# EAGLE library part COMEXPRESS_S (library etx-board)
ETX Express COM Express Device generated with split-gate-in-device-to-single-gates.ulp from C-5353652-36-3.dev at 04.12.08 14:01:30 with EAGLE Version 5.3.5 Copyright (c) 1988-2008 CadSoft Source: http://catalog.tycoelectronics.com .. ENG_CS_889092_0.5mm_FH_Conn_0906.pdf http://nordic.kontron.com/searchresult/?searchterm=etxe_designguide_v1.4.pdf
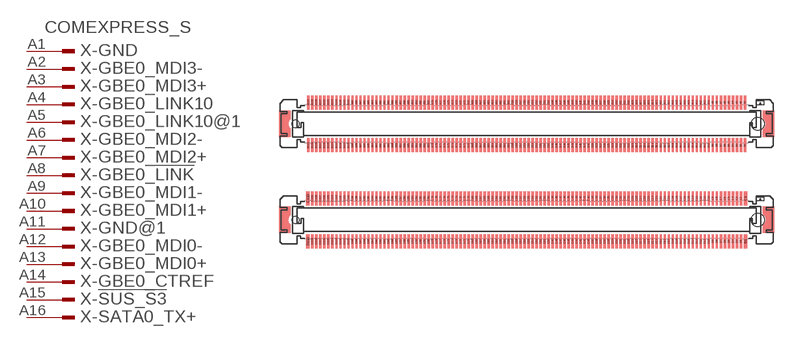
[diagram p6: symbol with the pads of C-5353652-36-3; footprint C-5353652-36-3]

Designator prefix X; gates -GND=1PIN_NAME_VALUE -GBE0_MDI3-=1PIN_NAME -GBE0_MDI3+=1PIN_NAME -GBE0_LINK10=1PIN_NAME -GBE0_LINK10@1=1PIN_NAME -GBE0_MDI2-=1PIN_NAME -GBE0_MDI2+=1PIN_NAME -GBE0_!LINK=1PIN_NAME -GBE0_MDI1-=1PIN_NAME -GBE0_MDI1+=1PIN_NAME -GND@1=1PIN_NAME -GBE0_MDI0-=1PIN_NAME -GBE0_MDI0+=1PIN_NAME -GBE0_CTREF=1PIN_NAME -!SUS_S3=1PIN_NAME -SATA0_TX+=1PIN_NAME -SATA0_TX-=1PIN_NAME -!SUS_S4=1PIN_NAME -SATA0_RX+=1PIN_NAME -SATA0_RX-=1PIN_NAME -GND@2=1PIN_NAME -SATA2_TX+=1PIN_NAME -SATA2_TX-=1PIN_NAME -!SUS_S5=1PIN_NAME -SATA2_RX+=1PIN_NAME -SATA2_RX-=1PIN_NAME -!BATLOW=1PIN_NAME -!ATA_ACT=1PIN_NAME -AC_SYNC=1PIN_NAME -!AC_RST=1PIN_NAME -GND@3=1PIN_NAME -AC_BITCLK=1PIN_NAME -AC_SDOUT=1PIN_NAME -BIOS_DISABLE=1PIN_NAME -!THRMTRIP=1PIN_NAME -USB6-=1PIN_NAME -USB6+=1PIN_NAME -!USB_6_7_OC=1PIN_NAME -USB4-=1PIN_NAME -USB4+=1PIN_NAME -GND@4=1PIN_NAME -USB2-=1PIN_NAME -USB2+=1PIN_NAME -!USB_2_3_OC=1PIN_NAME -USB0-=1PIN_NAME -USB0+=1PIN_NAME -VCC_RTC=1PIN_NAME -!EXCD0_PERST=1PIN_NAME -!EXCD0_CPPE=1PIN_NAME -LPC_SERIRQ=1PIN_NAME -GND@5=1PIN_NAME -PCIE_TX5+=1PIN_NAME -PCIE_TX5-=1PIN_NAME -GPI0=1PIN_NAME -PCIE_TX4+=1PIN_NAME -PCIE_TX4-=1PIN_NAME -GND@6=1PIN_NAME -PCIE_TX3+=1PIN_NAME -PCIE_TX3-=1PIN_NAME -GND@7=1PIN_NAME -PCIE_TX2+=1PIN_NAME -PCIE_TX2-=1PIN_NAME -GPI1=1PIN_NAME -PCIE_TX1+=1PIN_NAME -PCIE_TX1-=1PIN_NAME -GND@8=1PIN_NAME -GPI2=1PIN_NAME -PCIE_TX0+=1PIN_NAME -PCIE_TX0-=1PIN_NAME -GND@9=1PIN_NAME -LVDS_A0+=1PIN_NAME -LVDS_A0-=1PIN_NAME -LVDS_A1+=1PIN_NAME -LVDS_A1-=1PIN_NAME -LVDS_A2+=1PIN_NAME -LVDS_A2-=1PIN_NAME -LVDS_VDD_EN=1PIN_NAME -LVDS_A3+=1PIN_NAME -LVDS_A3-=1PIN_NAME -GND@10=1PIN_NAME -LVDS_A_CK+=1PIN_NAME -LVDS_A_CK-=1PIN_NAME -LVDS_I2C_CK=1PIN_NAME -LVDS_I2C_DAT=1PIN_NAME -GPI3=1PIN_NAME -!KBD_RST=1PIN_NAME -KBD_A20GATE=1PIN_NAME -PCIE0_CK_REF+=1PIN_NAME -PCIE0_CK_REF-=1PIN_NAME -GND@11=1PIN_NAME -RSVD=1PIN_NAME -RSVD@1=1PIN_NAME -GPO0=1PIN_NAME -RSVD@2=1PIN_NAME -RSVD@3=1PIN_NAME -GND@12=1PIN_NAME -VCC_12V=1PIN_NAME -VCC_12V@1=1PIN_NAME -VCC_12V@2=1PIN_NAME -GND@13=1PIN_NAME -VCC_12V@3=1PIN_NAME -VCC_12V@4=1PIN_NAME -VCC_12V@5=1PIN_NAME -VCC_12V@6=1PIN_NAME -VCC_12V@7=1PIN_NAME -VCC_12V@8=1PIN_NAME -VCC_12V@9=1PIN_NAME -VCC_12V@10=1PIN_NAME -VCC_12V@11=1PIN_NAME -GND@14=1PIN_NAME -GND@15=1PIN_NAME -GBE0_ACT=1PIN_NAME -LPC_FRAME!=1PIN_NAME -LPC_AD0=1PIN_NAME -LPC_AD1=1PIN_NAME -LPC_AD2=1PIN_NAME -LPC_AD3=1PIN_NAME -!LPC_DRQ0=1PIN_NAME -LPC_DRQ1!=1PIN_NAME -LPC_CLK=1PIN_NAME -GND@16=1PIN_NAME -!PWRBTN=1PIN_NAME -SMB_CK=1PIN_NAME -SMB_DAT=1PIN_NAME -SMB_ALERT!=1PIN_NAME -SATA1_TX+=1PIN_NAME -SATA1_TX-=1PIN_NAME -SUS_STAT!=1PIN_NAME -SATA1_RX+=1PIN_NAME -SATA1_RX-=1PIN_NAME -GND@17=1PIN_NAME -SATA3_TX+=1PIN_NAME -SATA3_TX-=1PIN_NAME -PWR_OK=1PIN_NAME -SATA3_RX+=1PIN_NAME -SATA3_RX-=1PIN_NAME -WDT=1PIN_NAME -AC_SDIN2=1PIN_NAME -AC_SDIN1=1PIN_NAME -AC_SDIN0=1PIN_NAME -GND@18=1PIN_NAME -SPKR=1PIN_NAME -I2C_CK=1PIN_NAME -I2C_DAT=1PIN_NAME -THRM!=1PIN_NAME -USB7-=1PIN_NAME -USB7+=1PIN_NAME -!USB_4_5_OC=1PIN_NAME -USB5-=1PIN_NAME -USB5+=1PIN_NAME -GND@19=1PIN_NAME -USB3-=1PIN_NAME -USB3+=1PIN_NAME -!USB_0_1_OC=1PIN_NAME -USB1-=1PIN_NAME -USB1+=1PIN_NAME -!EXCD1_PERST=1PIN_NAME -!EXCD1_CPPE=1PIN_NAME -!SYS_RESET=1PIN_NAME -!CB_RESET=1PIN_NAME -GND@20=1PIN_NAME -PCIE_RX5+=1PIN_NAME -PCIE_RX5-=1PIN_NAME -GPO1=1PIN_NAME -PCIE_RX4+=1PIN_NAME -PCIE_RX4-=1PIN_NAME -GPO2=1PIN_NAME -PCIE_RX3+=1PIN_NAME -PCIE_RX3-=1PIN_NAME -GND@21=1PIN_NAME -PCIE_RX2+=1PIN_NAME -PCIE_RX2-=1PIN_NAME -GPO3=1PIN_NAME -PCIE_RX1+=1PIN_NAME -PCIE_RX1-=1PIN_NAME -!WAKE0=1PIN_NAME -!WAKE1=1PIN_NAME -PCIE_RX0+=1PIN_NAME -PCIE_RX0-=1PIN_NAME -GND@22=1PIN_NAME -LVDS_B0+=1PIN_NAME -LVDS_B0-=1PIN_NAME -LVDS_B1+=1PIN_NAME -LVDS_B1-=1PIN_NAME -LVDS_B2+=1PIN_NAME -LVDS_B2-=1PIN_NAME -LVDS_B3+=1PIN_NAME -LVDS_B3-=1PIN_NAME -LVDS_BKLT_EN=1PIN_NAME -GND@23=1PIN_NAME -LVDS_B_CK+=1PIN_NAME -LVDS_B_CK-=1PIN_NAME -LVDS_BKLT_CTRL=1PIN_NAME -VCC_5V_SBY=1PIN_NAME -VCC_5V_SBY@1=1PIN_NAME -VCC_5V_SBY@2=1PIN_NAME -VCC_5V_SBY@3=1PIN_NAME -RSVD@4=1PIN_NAME -VGA_RED=1PIN_NAME -GND@24=1PIN_NAME -VGA_GRN=1PIN_NAME -VGA_BLU=1PIN_NAME -VGA_HSYNC=1PIN_NAME -VGA_VSYNC=1PIN_NAME -VGA_I2C_CK=1PIN_NAME -VGA_I2C_DAT=1PIN_NAME -TV_DAC_A=1PIN_NAME -TV_DAC_B=1PIN_NAME -TV_DAC_C=1PIN_NAME -GND@25=1PIN_NAME -VCC_12V@12=1PIN_NAME -VCC_12V@13=1PIN_NAME -VCC_12V@14=1PIN_NAME -VCC_12V@15=1PIN_NAME -VCC_12V@16=1PIN_NAME -VCC_12V@17=1PIN_NAME -VCC_12V@18=1PIN_NAME -VCC_12V@19=1PIN_NAME -VCC_12V@20=1PIN_NAME -GND@26=1PIN_NAME -GND@27=1PIN_NAME -IDE_D7=1PIN_NAME -IDE_D6=1PIN_NAME -IDE_D3=1PIN_NAME -IDE_D15=1PIN_NAME -IDE_D8=1PIN_NAME -IDE_D9=1PIN_NAME -IDE_D2=1PIN_NAME -IDE_D13=1PIN_NAME -IDE_D1=1PIN_NAME -GND@28=1PIN_NAME -IDE_D14=1PIN_NAME -IDE_IORDY=1PIN_NAME -!IDE_IOR=1PIN_NAME -!PCI_PME=1PIN_NAME -!PCI_GNT2=1PIN_NAME -!PCI_REQ2=1PIN_NAME -!PCI_GNT1=1PIN_NAME -!PCI_REQ1=1PIN_NAME -!PCI_GNT0=1PIN_NAME -GND@29=1PIN_NAME -!PCI_REQ0=1PIN_NAME -!PCI_RST=1PIN_NAME -PCI_AD0=1PIN_NAME -PCI_AD2=1PIN_NAME -PCI_AD4=1PIN_NAME -PCI_AD6=1PIN_NAME -PCI_AD8=1PIN_NAME -PCI_AD10=1PIN_NAME -PCI_AD12=1PIN_NAME -GND@30=1PIN_NAME -PCI_AD14=1PIN_NAME -PCI_C/!BE1=1PIN_NAME -!PCI_PERR=1PIN_NAME -!PCI_LOCK=1PIN_NAME -!PCI_DEVSEL=1PIN_NAME -!PCI_IRDY=1PIN_NAME -PCI_C/!BE2=1PIN_NAME -PCI_AD17=1PIN_NAME -PCI_AD19=1PIN_NAME -GND@31=1PIN_NAME -PCI_AD21=1PIN_NAME -PCI_AD23=1PIN_NAME -PCI_C/!BE3=1PIN_NAME -PCI_AD25=1PIN_NAME -PCI_AD27=1PIN_NAME -PCI_AD29=1PIN_NAME -PCI_AD31=1PIN_NAME -!PCI_IRQA=1PIN_NAME -!PCI_IRQB=1PIN_NAME -GND@32=1PIN_NAME -PEG_RX0+=1PIN_NAME -PEG_RX0-=1PIN_NAME -!TYPE0=1PIN_NAME -PEG_RX1+=1PIN_NAME -PEG_RX1-=1PIN_NAME -!TYPE1=1PIN_NAME -PEG_RX2+=1PIN_NAME -PEG_RX2-=1PIN_NAME -GND@33=1PIN_NAME -PEG_RX3+=1PIN_NAME -PEG_RX3-=1PIN_NAME -RSVD@5=1PIN_NAME -RSVD@6=1PIN_NAME -PEG_RX4+=1PIN_NAME -PEG_RX4-=1PIN_NAME -RSVD@7=1PIN_NAME -PEG_RX5+=1PIN_NAME -PEG_RX5-=1PIN_NAME -GND@34=1PIN_NAME -PEG_RX6+=1PIN_NAME -PEG_RX6-=1PIN_NAME -SDVO_DATA=1PIN_NAME -PEG_RX7+=1PIN_NAME -PEG_RX7-=1PIN_NAME -GND@35=1PIN_NAME -RSVD@8=1PIN_NAME -PEG_RX8+=1PIN_NAME -PEG_RX8-=1PIN_NAME -GND@36=1PIN_NAME -PEG_RX9+=1PIN_NAME -PEG_RX9-=1PIN_NAME -RSVD@9=1PIN_NAME -GND@37=1PIN_NAME -PEG_RX10+=1PIN_NAME -PEG_RX10-=1PIN_NAME -GND@38=1PIN_NAME -PEG_RX11+=1PIN_NAME -PEG_RX11-=1PIN_NAME -GND@39=1PIN_NAME -PEG_RX12+=1PIN_NAME -PEG_RX12-=1PIN_NAME -GND@40=1PIN_NAME -PEG_RX13+=1PIN_NAME -PEG_RX13-=1PIN_NAME -GND@41=1PIN_NAME -RSVD@10=1PIN_NAME -PEG_RX14+=1PIN_NAME -PEG_RX14-=1PIN_NAME -GND@42=1PIN_NAME -PEG_RX15+=1PIN_NAME -PEG_RX15-=1PIN_NAME -GND@43=1PIN_NAME -VCC_12V@21=1PIN_NAME -VCC_12V@22=1PIN_NAME -VCC_12V@23=1PIN_NAME -VCC_12V@24=1PIN_NAME -VCC_12V@25=1PIN_NAME -VCC_12V@26=1PIN_NAME -GND@44=1PIN_NAME -GND@45=1PIN_NAME -IDE_D5=1PIN_NAME -IDE_D10=1PIN_NAME -IDE_D11=1PIN_NAME -IDE_D12=1PIN_NAME -IDE_D4=1PIN_NAME -IDE_D0=1PIN_NAME -IDE_REQ=1PIN_NAME -!IDE_IOW=1PIN_NAME -!IDE_ACK=1PIN_NAME -GND@46=1PIN_NAME -IDE_IRQ=1PIN_NAME -IDE_A0=1PIN_NAME -IDE_A1=1PIN_NAME -IDE_A2=1PIN_NAME -!IDE_CS1=1PIN_NAME -!IDE_CS3=1PIN_NAME -!IDE_RESET=1PIN_NAME -!PCI_GNT3=1PIN_NAME -!PCI_REQ3=1PIN_NAME -GND@47=1PIN_NAME -PCI_AD1=1PIN_NAME -PCI_AD3=1PIN_NAME -PCI_AD5=1PIN_NAME -PCI_AD7=1PIN_NAME -PCI_C/!BE0=1PIN_NAME -PCI_AD9=1PIN_NAME -PCI_AD11=1PIN_NAME -PCI_AD13=1PIN_NAME -PCI_AD15=1PIN_NAME -GND@48=1PIN_NAME -PCI_PAR=1PIN_NAME -!PCI_SERR=1PIN_NAME -!PCI_STOP=1PIN_NAME -!PCI_TRDY=1PIN_NAME -!PCI_FRAME=1PIN_NAME -PCI_AD16=1PIN_NAME -PCI_AD18=1PIN_NAME -PCI_AD20=1PIN_NAME -PCI_AD22=1PIN_NAME -GND@49=1PIN_NAME -PCI_AD24=1PIN_NAME -PCI_AD26=1PIN_NAME -PCI_AD28=1PIN_NAME -PCI_AD30=1PIN_NAME -!PCI_IRQC=1PIN_NAME -!PCI_IRQD=1PIN_NAME -!PCI_CLKRUN=1PIN_NAME -PCI_M66EN=1PIN_NAME -PCI_CLK=1PIN_NAME -GND@50=1PIN_NAME -PEG_TX0+=1PIN_NAME -PEG_TX0-=1PIN_NAME -!PEG_LANE_RV=1PIN_NAME -PEG_TX1+=1PIN_NAME -PEG_TX1-=1PIN_NAME -!TYPE2=1PIN_NAME -PEG_TX2+=1PIN_NAME -PEG_TX2-=1PIN_NAME -GND@51=1PIN_NAME -PEG_TX3+=1PIN_NAME -PEG_TX3-=1PIN_NAME -RSVD@11=1PIN_NAME -RSVD@12=1PIN_NAME -PEG_TX4+=1PIN_NAME -PEG_TX4-=1PIN_NAME -GND@52=1PIN_NAME -PEG_TX5+=1PIN_NAME -PEG_TX5-=1PIN_NAME -GND@53=1PIN_NAME -PEG_TX6+=1PIN_NAME -PEG_TX6-=1PIN_NAME -SDVO_CLK=1PIN_NAME -PEG_TX7+=1PIN_NAME -PEG_TX7-=1PIN_NAME -GND@54=1PIN_NAME -IDE_CBLID=1PIN_NAME -PEG_TX8+=1PIN_NAME -PEG_TX8-=1PIN_NAME -GND@55=1PIN_NAME -PEG_TX9+=1PIN_NAME -PEG_TX9-=1PIN_NAME -RSVD@13=1PIN_NAME -GND@56=1PIN_NAME -PEG_TX10+=1PIN_NAME -PEG_TX10-=1PIN_NAME -GND@57=1PIN_NAME -PEG_TX11+=1PIN_NAME -PEG_TX11-=1PIN_NAME -GND@58=1PIN_NAME -PEG_TX12+=1PIN_NAME -PEG_TX12-=1PIN_NAME -GND@59=1PIN_NAME -PEG_TX13+=1PIN_NAME -PEG_TX13-=1PIN_NAME -GND@60=1PIN_NAME -!PEG_ENABLE=1PIN_NAME -PEG_TX14+=1PIN_NAME -PEG_TX14-=1PIN_NAME -GND@61=1PIN_NAME -PEG_TX15+=1PIN_NAME -PEG_TX15-=1PIN_NAME -GND@62=1PIN_NAME -VCC_12V@27=1PIN_NAME -VCC_12V@28=1PIN_NAME -VCC_12V@29=1PIN_NAME -VCC_12V@30=1PIN_NAME -VCC_12V@31=1PIN_NAME -VCC_12V@32=1PIN_NAME -GND@63=1PIN_NAME

## COMEXPRESS_S  [C-5353652-36-3]
A1  -GND:1  pas
A2  -GBE0_MDI3-:1  pas
A3  -GBE0_MDI3+:1  pas
A4  -GBE0_LINK10:1  pas
A5  -GBE0_LINK10@1:1  pas
A6  -GBE0_MDI2-:1  pas
A7  -GBE0_MDI2+:1  pas
A8  -GBE0_!LINK:1  pas
A9  -GBE0_MDI1-:1  pas
A10  -GBE0_MDI1+:1  pas
A11  -GND@1:1  pas
A12  -GBE0_MDI0-:1  pas
A13  -GBE0_MDI0+:1  pas
A14  -GBE0_CTREF:1  pas
A15  -!SUS_S3:1  pas
A16  -SATA0_TX+:1  pas
A17  -SATA0_TX-:1  pas
A18  -!SUS_S4:1  pas
A19  -SATA0_RX+:1  pas
A20  -SATA0_RX-:1  pas
A21  -GND@2:1  pas
A22  -SATA2_TX+:1  pas
A23  -SATA2_TX-:1  pas
A24  -!SUS_S5:1  pas
A25  -SATA2_RX+:1  pas
A26  -SATA2_RX-:1  pas
A27  -!BATLOW:1  pas
A28  -!ATA_ACT:1  pas
A29  -AC_SYNC:1  pas
A30  -!AC_RST:1  pas
A31  -GND@3:1  pas
A32  -AC_BITCLK:1  pas
A33  -AC_SDOUT:1  pas
A34  -BIOS_DISABLE:1  pas
A35  -!THRMTRIP:1  pas
A36  -USB6-:1  pas
A37  -USB6+:1  pas
A38  -!USB_6_7_OC:1  pas
A39  -USB4-:1  pas
A40  -USB4+:1  pas
A41  -GND@4:1  pas
A42  -USB2-:1  pas
A43  -USB2+:1  pas
A44  -!USB_2_3_OC:1  pas
A45  -USB0-:1  pas
A46  -USB0+:1  pas
A47  -VCC_RTC:1  pas
A48  -!EXCD0_PERST:1  pas
A49  -!EXCD0_CPPE:1  pas
A50  -LPC_SERIRQ:1  pas
A51  -GND@5:1  pas
A52  -PCIE_TX5+:1  pas
A53  -PCIE_TX5-:1  pas
A54  -GPI0:1  pas
A55  -PCIE_TX4+:1  pas
A56  -PCIE_TX4-:1  pas
A57  -GND@6:1  pas
A58  -PCIE_TX3+:1  pas
A59  -PCIE_TX3-:1  pas
A60  -GND@7:1  pas
A61  -PCIE_TX2+:1  pas
A62  -PCIE_TX2-:1  pas
A63  -GPI1:1  pas
A64  -PCIE_TX1+:1  pas
A65  -PCIE_TX1-:1  pas
A66  -GND@8:1  pas
A67  -GPI2:1  pas
A68  -PCIE_TX0+:1  pas
A69  -PCIE_TX0-:1  pas
A70  -GND@9:1  pas
A71  -LVDS_A0+:1  pas
A72  -LVDS_A0-:1  pas
A73  -LVDS_A1+:1  pas
A74  -LVDS_A1-:1  pas
A75  -LVDS_A2+:1  pas
A76  -LVDS_A2-:1  pas
A77  -LVDS_VDD_EN:1  pas
A78  -LVDS_A3+:1  pas
A79  -LVDS_A3-:1  pas
A80  -GND@10:1  pas
A81  -LVDS_A_CK+:1  pas
A82  -LVDS_A_CK-:1  pas
A83  -LVDS_I2C_CK:1  pas
A84  -LVDS_I2C_DAT:1  pas
A85  -GPI3:1  pas
A86  -!KBD_RST:1  pas
A87  -KBD_A20GATE:1  pas
A88  -PCIE0_CK_REF+:1  pas
A89  -PCIE0_CK_REF-:1  pas
A90  -GND@11:1  pas
A91  -RSVD:1  pas
A92  -RSVD@1:1  pas
A93  -GPO0:1  pas
A94  -RSVD@2:1  pas
A95  -RSVD@3:1  pas
A96  -GND@12:1  pas
A97  -VCC_12V:1  pas
A98  -VCC_12V@1:1  pas
A99  -VCC_12V@2:1  pas
A100  -GND@13:1  pas
A101  -VCC_12V@3:1  pas
A102  -VCC_12V@4:1  pas
A103  -VCC_12V@5:1  pas
A104  -VCC_12V@6:1  pas
A105  -VCC_12V@7:1  pas
A106  -VCC_12V@8:1  pas
A107  -VCC_12V@9:1  pas
A108  -VCC_12V@10:1  pas
A109  -VCC_12V@11:1  pas
A110  -GND@14:1  pas
B1  -GND@15:1  pas
B2  -GBE0_ACT:1  pas
B3  -LPC_FRAME!:1  pas
B4  -LPC_AD0:1  pas
B5  -LPC_AD1:1  pas
B6  -LPC_AD2:1  pas
B7  -LPC_AD3:1  pas
B8  -!LPC_DRQ0:1  pas
B9  -LPC_DRQ1!:1  pas
B10  -LPC_CLK:1  pas
B11  -GND@16:1  pas
B12  -!PWRBTN:1  pas
B13  -SMB_CK:1  pas
B14  -SMB_DAT:1  pas
B15  -SMB_ALERT!:1  pas
B16  -SATA1_TX+:1  pas
B17  -SATA1_TX-:1  pas
B18  -SUS_STAT!:1  pas
B19  -SATA1_RX+:1  pas
B20  -SATA1_RX-:1  pas
B21  -GND@17:1  pas
B22  -SATA3_TX+:1  pas
B23  -SATA3_TX-:1  pas
B24  -PWR_OK:1  pas
B25  -SATA3_RX+:1  pas
B26  -SATA3_RX-:1  pas
B27  -WDT:1  pas
B28  -AC_SDIN2:1  pas
B29  -AC_SDIN1:1  pas
B30  -AC_SDIN0:1  pas
B31  -GND@18:1  pas
B32  -SPKR:1  pas
B33  -I2C_CK:1  pas
B34  -I2C_DAT:1  pas
B35  -THRM!:1  pas
B36  -USB7-:1  pas
B37  -USB7+:1  pas
B38  -!USB_4_5_OC:1  pas
B39  -USB5-:1  pas
B40  -USB5+:1  pas
B41  -GND@19:1  pas
B42  -USB3-:1  pas
B43  -USB3+:1  pas
B44  -!USB_0_1_OC:1  pas
B45  -USB1-:1  pas
B46  -USB1+:1  pas
B47  -!EXCD1_PERST:1  pas
B48  -!EXCD1_CPPE:1  pas
B49  -!SYS_RESET:1  pas
B50  -!CB_RESET:1  pas
B51  -GND@20:1  pas
B52  -PCIE_RX5+:1  pas
B53  -PCIE_RX5-:1  pas
B54  -GPO1:1  pas
B55  -PCIE_RX4+:1  pas
B56  -PCIE_RX4-:1  pas
B57  -GPO2:1  pas
B58  -PCIE_RX3+:1  pas
B59  -PCIE_RX3-:1  pas
B60  -GND@21:1  pas
B61  -PCIE_RX2+:1  pas
B62  -PCIE_RX2-:1  pas
B63  -GPO3:1  pas
B64  -PCIE_RX1+:1  pas
B65  -PCIE_RX1-:1  pas
B66  -!WAKE0:1  pas
B67  -!WAKE1:1  pas
B68  -PCIE_RX0+:1  pas
B69  -PCIE_RX0-:1  pas
B70  -GND@22:1  pas
B71  -LVDS_B0+:1  pas
B72  -LVDS_B0-:1  pas
B73  -LVDS_B1+:1  pas
B74  -LVDS_B1-:1  pas
B75  -LVDS_B2+:1  pas
B76  -LVDS_B2-:1  pas
B77  -LVDS_B3+:1  pas
B78  -LVDS_B3-:1  pas
B79  -LVDS_BKLT_EN:1  pas
B80  -GND@23:1  pas
B81  -LVDS_B_CK+:1  pas
B82  -LVDS_B_CK-:1  pas
B83  -LVDS_BKLT_CTRL:1  pas
B84  -VCC_5V_SBY:1  pas
B85  -VCC_5V_SBY@1:1  pas
B86  -VCC_5V_SBY@2:1  pas
B87  -VCC_5V_SBY@3:1  pas
B88  -RSVD@4:1  pas
B89  -VGA_RED:1  pas
B90  -GND@24:1  pas
B91  -VGA_GRN:1  pas
B92  -VGA_BLU:1  pas
B93  -VGA_HSYNC:1  pas
B94  -VGA_VSYNC:1  pas
B95  -VGA_I2C_CK:1  pas
B96  -VGA_I2C_DAT:1  pas
B97  -TV_DAC_A:1  pas
B98  -TV_DAC_B:1  pas
B99  -TV_DAC_C:1  pas
B100  -GND@25:1  pas
B101  -VCC_12V@12:1  pas
B102  -VCC_12V@13:1  pas
B103  -VCC_12V@14:1  pas
B104  -VCC_12V@15:1  pas
B105  -VCC_12V@16:1  pas
B106  -VCC_12V@17:1  pas
B107  -VCC_12V@18:1  pas
B108  -VCC_12V@19:1  pas
B109  -VCC_12V@20:1  pas
B110  -GND@26:1  pas
C1  -GND@27:1  pas
C2  -IDE_D7:1  pas
C3  -IDE_D6:1  pas
C4  -IDE_D3:1  pas
C5  -IDE_D15:1  pas
C6  -IDE_D8:1  pas
C7  -IDE_D9:1  pas
C8  -IDE_D2:1  pas
C9  -IDE_D13:1  pas
C10  -IDE_D1:1  pas
C11  -GND@28:1  pas
C12  -IDE_D14:1  pas
C13  -IDE_IORDY:1  pas
C14  -!IDE_IOR:1  pas
C15  -!PCI_PME:1  pas
C16  -!PCI_GNT2:1  pas
C17  -!PCI_REQ2:1  pas
C18  -!PCI_GNT1:1  pas
C19  -!PCI_REQ1:1  pas
C20  -!PCI_GNT0:1  pas
C21  -GND@29:1  pas
C22  -!PCI_REQ0:1  pas
C23  -!PCI_RST:1  pas
C24  -PCI_AD0:1  pas
C25  -PCI_AD2:1  pas
C26  -PCI_AD4:1  pas
C27  -PCI_AD6:1  pas
C28  -PCI_AD8:1  pas
C29  -PCI_AD10:1  pas
C30  -PCI_AD12:1  pas
C31  -GND@30:1  pas
C32  -PCI_AD14:1  pas
C33  -PCI_C/!BE1:1  pas
C34  -!PCI_PERR:1  pas
C35  -!PCI_LOCK:1  pas
C36  -!PCI_DEVSEL:1  pas
C37  -!PCI_IRDY:1  pas
C38  -PCI_C/!BE2:1  pas
C39  -PCI_AD17:1  pas
C40  -PCI_AD19:1  pas
C41  -GND@31:1  pas
C42  -PCI_AD21:1  pas
C43  -PCI_AD23:1  pas
C44  -PCI_C/!BE3:1  pas
C45  -PCI_AD25:1  pas
C46  -PCI_AD27:1  pas
C47  -PCI_AD29:1  pas
C48  -PCI_AD31:1  pas
C49  -!PCI_IRQA:1  pas
C50  -!PCI_IRQB:1  pas
C51  -GND@32:1  pas
C52  -PEG_RX0+:1  pas
C53  -PEG_RX0-:1  pas
C54  -!TYPE0:1  pas
C55  -PEG_RX1+:1  pas
C56  -PEG_RX1-:1  pas
C57  -!TYPE1:1  pas
C58  -PEG_RX2+:1  pas
C59  -PEG_RX2-:1  pas
C60  -GND@33:1  pas
C61  -PEG_RX3+:1  pas
C62  -PEG_RX3-:1  pas
C63  -RSVD@5:1  pas
C64  -RSVD@6:1  pas
C65  -PEG_RX4+:1  pas
C66  -PEG_RX4-:1  pas
C67  -RSVD@7:1  pas
C68  -PEG_RX5+:1  pas
C69  -PEG_RX5-:1  pas
C70  -GND@34:1  pas
C71  -PEG_RX6+:1  pas
C72  -PEG_RX6-:1  pas
C73  -SDVO_DATA:1  pas
C74  -PEG_RX7+:1  pas
C75  -PEG_RX7-:1  pas
C76  -GND@35:1  pas
C77  -RSVD@8:1  pas
C78  -PEG_RX8+:1  pas
C79  -PEG_RX8-:1  pas
C80  -GND@36:1  pas
C81  -PEG_RX9+:1  pas
C82  -PEG_RX9-:1  pas
C83  -RSVD@9:1  pas
C84  -GND@37:1  pas
C85  -PEG_RX10+:1  pas
C86  -PEG_RX10-:1  pas
C87  -GND@38:1  pas
C88  -PEG_RX11+:1  pas
C89  -PEG_RX11-:1  pas
C90  -GND@39:1  pas
C91  -PEG_RX12+:1  pas
C92  -PEG_RX12-:1  pas
C93  -GND@40:1  pas
C94  -PEG_RX13+:1  pas
C95  -PEG_RX13-:1  pas
C96  -GND@41:1  pas
C97  -RSVD@10:1  pas
C98  -PEG_RX14+:1  pas
C99  -PEG_RX14-:1  pas
C100  -GND@42:1  pas
C101  -PEG_RX15+:1  pas
C102  -PEG_RX15-:1  pas
C103  -GND@43:1  pas
C104  -VCC_12V@21:1  pas
C105  -VCC_12V@22:1  pas
C106  -VCC_12V@23:1  pas
C107  -VCC_12V@24:1  pas
C108  -VCC_12V@25:1  pas
C109  -VCC_12V@26:1  pas
C110  -GND@44:1  pas
D1  -GND@45:1  pas
D2  -IDE_D5:1  pas
D3  -IDE_D10:1  pas
D4  -IDE_D11:1  pas
D5  -IDE_D12:1  pas
D6  -IDE_D4:1  pas
D7  -IDE_D0:1  pas
D8  -IDE_REQ:1  pas
D9  -!IDE_IOW:1  pas
D10  -!IDE_ACK:1  pas
D11  -GND@46:1  pas
D12  -IDE_IRQ:1  pas
D13  -IDE_A0:1  pas
D14  -IDE_A1:1  pas
D15  -IDE_A2:1  pas
D16  -!IDE_CS1:1  pas
D17  -!IDE_CS3:1  pas
D18  -!IDE_RESET:1  pas
D19  -!PCI_GNT3:1  pas
D20  -!PCI_REQ3:1  pas
D21  -GND@47:1  pas
D22  -PCI_AD1:1  pas
D23  -PCI_AD3:1  pas
D24  -PCI_AD5:1  pas
D25  -PCI_AD7:1  pas
D26  -PCI_C/!BE0:1  pas
D27  -PCI_AD9:1  pas
D28  -PCI_AD11:1  pas
D29  -PCI_AD13:1  pas
D30  -PCI_AD15:1  pas
D31  -GND@48:1  pas
D32  -PCI_PAR:1  pas
D33  -!PCI_SERR:1  pas
D34  -!PCI_STOP:1  pas
D35  -!PCI_TRDY:1  pas
D36  -!PCI_FRAME:1  pas
D37  -PCI_AD16:1  pas
D38  -PCI_AD18:1  pas
D39  -PCI_AD20:1  pas
D40  -PCI_AD22:1  pas
D41  -GND@49:1  pas
D42  -PCI_AD24:1  pas
D43  -PCI_AD26:1  pas
D44  -PCI_AD28:1  pas
D45  -PCI_AD30:1  pas
D46  -!PCI_IRQC:1  pas
D47  -!PCI_IRQD:1  pas
D48  -!PCI_CLKRUN:1  pas
D49  -PCI_M66EN:1  pas
D50  -PCI_CLK:1  pas
D51  -GND@50:1  pas
D52  -PEG_TX0+:1  pas
D53  -PEG_TX0-:1  pas
D54  -!PEG_LANE_RV:1  pas
D55  -PEG_TX1+:1  pas
D56  -PEG_TX1-:1  pas
D57  -!TYPE2:1  pas
D58  -PEG_TX2+:1  pas
D59  -PEG_TX2-:1  pas
D60  -GND@51:1  pas
D61  -PEG_TX3+:1  pas
D62  -PEG_TX3-:1  pas
D63  -RSVD@11:1  pas
D64  -RSVD@12:1  pas
D65  -PEG_TX4+:1  pas
D66  -PEG_TX4-:1  pas
D67  -GND@52:1  pas
D68  -PEG_TX5+:1  pas
D69  -PEG_TX5-:1  pas
D70  -GND@53:1  pas
D71  -PEG_TX6+:1  pas
D72  -PEG_TX6-:1  pas
D73  -SDVO_CLK:1  pas
D74  -PEG_TX7+:1  pas
D75  -PEG_TX7-:1  pas
D76  -GND@54:1  pas
D77  -IDE_CBLID:1  pas
D78  -PEG_TX8+:1  pas
D79  -PEG_TX8-:1  pas
D80  -GND@55:1  pas
D81  -PEG_TX9+:1  pas
D82  -PEG_TX9-:1  pas
D83  -RSVD@13:1  pas
D84  -GND@56:1  pas
D85  -PEG_TX10+:1  pas
D86  -PEG_TX10-:1  pas
D87  -GND@57:1  pas
D88  -PEG_TX11+:1  pas
D89  -PEG_TX11-:1  pas
D90  -GND@58:1  pas
D91  -PEG_TX12+:1  pas
D92  -PEG_TX12-:1  pas
D93  -GND@59:1  pas
D94  -PEG_TX13+:1  pas
D95  -PEG_TX13-:1  pas
D96  -GND@60:1  pas
D97  -!PEG_ENABLE:1  pas
D98  -PEG_TX14+:1  pas
D99  -PEG_TX14-:1  pas
D100  -GND@61:1  pas
D101  -PEG_TX15+:1  pas
D102  -PEG_TX15-:1  pas
D103  -GND@62:1  pas
D104  -VCC_12V@27:1  pas
D105  -VCC_12V@28:1  pas
D106  -VCC_12V@29:1  pas
D107  -VCC_12V@30:1  pas
D108  -VCC_12V@31:1  pas
D109  -VCC_12V@32:1  pas
D110  -GND@63:1  pas

## Footprint C-5353652-36-3 (pad centres in mm)
ComExpress (ETXexpress) Source: http://catalog.tycoelectronics.com .. ENG_CS_889092_0.5mm_FH_Conn_0906.pdf
smd 0.3 x 1.75: A1 27.25,8.675; A2 26.75,8.675; A3 26.25,8.675; A4 25.75,8.675; A5 25.25,8.675; A6 24.75,8.675; A7 24.25,8.675; A8 23.75,8.675; A9 23.25,8.675; A10 22.75,8.675; A11 22.25,8.675; A12 21.75,8.675; A13 21.25,8.675; A14 20.75,8.675; A15 20.25,8.675; A16 19.75,8.675; A17 19.25,8.675; A18 18.75,8.675; A19 18.25,8.675; A20 17.75,8.675; A21 17.25,8.675; A22 16.75,8.675; A23 16.25,8.675; A24 15.75,8.675; A25 15.25,8.675; A26 14.75,8.675; A27 14.25,8.675; A28 13.75,8.675; A29 13.25,8.675; A30 12.75,8.675; A31 12.25,8.675; A32 11.75,8.675; A33 11.25,8.675; A34 10.75,8.675; A35 10.25,8.675; A36 9.75,8.675; A37 9.25,8.675; A38 8.75,8.675; A39 8.25,8.675; A40 7.75,8.675; A41 7.25,8.675; A42 6.75,8.675; A43 6.25,8.675; A44 5.75,8.675; A45 5.25,8.675; A46 4.75,8.675; A47 4.25,8.675; A48 3.75,8.675; A49 3.25,8.675; A50 2.75,8.675; A51 2.25,8.675; A52 1.75,8.675; A53 1.25,8.675; A54 0.75,8.675; A55 0.25,8.675; A56 -0.25,8.675; A57 -0.75,8.675; A58 -1.25,8.675; A59 -1.75,8.675; A60 -2.25,8.675; A61 -2.75,8.675; A62 -3.25,8.675; A63 -3.75,8.675; A64 -4.25,8.675; A65 -4.75,8.675; A66 -5.25,8.675; A67 -5.75,8.675; A68 -6.25,8.675; A69 -6.75,8.675; A70 -7.25,8.675; A71 -7.75,8.675; A72 -8.25,8.675; A73 -8.75,8.675; A74 -9.25,8.675; A75 -9.75,8.675; A76 -10.25,8.675; A77 -10.75,8.675; A78 -11.25,8.675; A79 -11.75,8.675; A80 -12.25,8.675; A81 -12.75,8.675; A82 -13.25,8.675; A83 -13.75,8.675; A84 -14.25,8.675; A85 -14.75,8.675; A86 -15.25,8.675; A87 -15.75,8.675; A88 -16.25,8.675; A89 -16.75,8.675; A90 -17.25,8.675; A91 -17.75,8.675; A92 -18.25,8.675; A93 -18.75,8.675; A94 -19.25,8.675; A95 -19.75,8.675; A96 -20.25,8.675; A97 -20.75,8.675; A98 -21.25,8.675; A99 -21.75,8.675; A100 -22.25,8.675; A101 -22.75,8.675; A102 -23.25,8.675; A103 -23.75,8.675; A104 -24.25,8.675; A105 -24.75,8.675; A106 -25.25,8.675; A107 -25.75,8.675; A108 -26.25,8.675; A109 -26.75,8.675; A110 -27.25,8.675; B1 27.25,3.325; B2 26.75,3.325; B3 26.25,3.325; B4 25.75,3.325; B5 25.25,3.325; B6 24.75,3.325; B7 24.25,3.325; B8 23.75,3.325; B9 23.25,3.325; B10 22.75,3.325; B11 22.25,3.325; B12 21.75,3.325; B13 21.25,3.325; B14 20.75,3.325; B15 20.25,3.325; B16 19.75,3.325; B17 19.25,3.325; B18 18.75,3.325; B19 18.25,3.325; B20 17.75,3.325; B21 17.25,3.325; B22 16.75,3.325; B23 16.25,3.325; B24 15.75,3.325; B25 15.25,3.325; B26 14.75,3.325; B27 14.25,3.325; B28 13.75,3.325; B29 13.25,3.325; B30 12.75,3.325; B31 12.25,3.325; B32 11.75,3.325; B33 11.25,3.325; B34 10.75,3.325; B35 10.25,3.325; B36 9.75,3.325; B37 9.25,3.325; B38 8.75,3.325; B39 8.25,3.325; B40 7.75,3.325; B41 7.25,3.325; B42 6.75,3.325; B43 6.25,3.325; B44 5.75,3.325; B45 5.25,3.325; B46 4.75,3.325; B47 4.25,3.325; B48 3.75,3.325; B49 3.25,3.325; B50 2.75,3.325; B51 2.25,3.325; B52 1.75,3.325; B53 1.25,3.325; B54 0.75,3.325; B55 0.25,3.325; B56 -0.25,3.325; B57 -0.75,3.325; B58 -1.25,3.325; B59 -1.75,3.325; B60 -2.25,3.325; B61 -2.75,3.325; B62 -3.25,3.325; B63 -3.75,3.325; B64 -4.25,3.325; B65 -4.75,3.325; B66 -5.25,3.325; B67 -5.75,3.325; B68 -6.25,3.325; B69 -6.75,3.325; B70 -7.25,3.325; B71 -7.75,3.325; B72 -8.25,3.325; B73 -8.75,3.325; B74 -9.25,3.325; B75 -9.75,3.325; B76 -10.25,3.325; B77 -10.75,3.325; B78 -11.25,3.325; B79 -11.75,3.325; B80 -12.25,3.325; B81 -12.75,3.325; B82 -13.25,3.325; B83 -13.75,3.325; B84 -14.25,3.325; B85 -14.75,3.325; B86 -15.25,3.325; B87 -15.75,3.325; B88 -16.25,3.325; B89 -16.75,3.325; B90 -17.25,3.325; B91 -17.75,3.325; B92 -18.25,3.325; B93 -18.75,3.325; B94 -19.25,3.325; B95 -19.75,3.325; B96 -20.25,3.325; B97 -20.75,3.325; B98 -21.25,3.325; B99 -21.75,3.325; B100 -22.25,3.325; B101 -22.75,3.325; B102 -23.25,3.325; B103 -23.75,3.325; B104 -24.25,3.325; B105 -24.75,3.325; B106 -25.25,3.325; B107 -25.75,3.325; B108 -26.25,3.325; B109 -26.75,3.325; B110 -27.25,3.325; C2 26.75,-3.325; C3 26.25,-3.325; C4 25.75,-3.325; C5 25.25,-3.325; C6 24.75,-3.325; C7 24.25,-3.325; C8 23.75,-3.325; C9 23.25,-3.325; C10 22.75,-3.325; C11 22.25,-3.325; C12 21.75,-3.325; C13 21.25,-3.325; C14 20.75,-3.325; C15 20.25,-3.325; C16 19.75,-3.325; C17 19.25,-3.325; C18 18.75,-3.325; C19 18.25,-3.325; C20 17.75,-3.325; C21 17.25,-3.325; C22 16.75,-3.325; C23 16.25,-3.325; C24 15.75,-3.325; C25 15.25,-3.325; C26 14.75,-3.325; C27 14.25,-3.325; C28 13.75,-3.325; C29 13.25,-3.325; C30 12.75,-3.325; C31 12.25,-3.325; C32 11.75,-3.325; C33 11.25,-3.325; C34 10.75,-3.325; C35 10.25,-3.325; C36 9.75,-3.325; C37 9.25,-3.325; C38 8.75,-3.325; C39 8.25,-3.325; C40 7.75,-3.325; C41 7.25,-3.325; C42 6.75,-3.325; C43 6.25,-3.325; C44 5.75,-3.325; C45 5.25,-3.325; C46 4.75,-3.325; C47 4.25,-3.325; C48 3.75,-3.325; C49 3.25,-3.325; C50 2.75,-3.325; C51 2.25,-3.325; C52 1.75,-3.325; C53 1.25,-3.325; C54 0.75,-3.325; C55 0.25,-3.325; C56 -0.25,-3.325; C57 -0.75,-3.325; C58 -1.25,-3.325; C59 -1.75,-3.325; C60 -2.25,-3.325; C61 -2.75,-3.325; C62 -3.25,-3.325; C63 -3.75,-3.325; C64 -4.25,-3.325; C65 -4.75,-3.325; C66 -5.25,-3.325; C67 -5.75,-3.325; C68 -6.25,-3.325; C69 -6.75,-3.325; C70 -7.25,-3.325; C71 -7.75,-3.325; C72 -8.25,-3.325; C73 -8.75,-3.325; C74 -9.25,-3.325; C75 -9.75,-3.325; C76 -10.25,-3.325; C77 -10.75,-3.325; C78 -11.25,-3.325; C79 -11.75,-3.325; C80 -12.25,-3.325; C81 -12.75,-3.325; C82 -13.25,-3.325; C83 -13.75,-3.325; C84 -14.25,-3.325; C85 -14.75,-3.325; C86 -15.25,-3.325; C87 -15.75,-3.325; C88 -16.25,-3.325; C89 -16.75,-3.325; C90 -17.25,-3.325; C91 -17.75,-3.325; C92 -18.25,-3.325; C93 -18.75,-3.325; C94 -19.25,-3.325; C95 -19.75,-3.325; C96 -20.25,-3.325; C97 -20.75,-3.325; C98 -21.25,-3.325; C99 -21.75,-3.325; C100 -22.25,-3.325; C101 -22.75,-3.325; C102 -23.25,-3.325; C103 -23.75,-3.325; C104 -24.25,-3.325; C105 -24.75,-3.325; C106 -25.25,-3.325; C107 -25.75,-3.325; C108 -26.25,-3.325; C109 -26.75,-3.325; D2 26.75,-8.675; D3 26.25,-8.675; D4 25.75,-8.675; D5 25.25,-8.675; D6 24.75,-8.675; D7 24.25,-8.675; D8 23.75,-8.675; D9 23.25,-8.675; D10 22.75,-8.675; D11 22.25,-8.675; D12 21.75,-8.675; D13 21.25,-8.675; D14 20.75,-8.675; D15 20.25,-8.675; D16 19.75,-8.675; D17 19.25,-8.675; D18 18.75,-8.675; D19 18.25,-8.675; D20 17.75,-8.675; D21 17.25,-8.675; D22 16.75,-8.675; D23 16.25,-8.675; D24 15.75,-8.675; D25 15.25,-8.675; D26 14.75,-8.675; D27 14.25,-8.675; D28 13.75,-8.675; D29 13.25,-8.675; D30 12.75,-8.675; D31 12.25,-8.675; D32 11.75,-8.675; D33 11.25,-8.675; D34 10.75,-8.675; D35 10.25,-8.675; D36 9.75,-8.675; D37 9.25,-8.675; D38 8.75,-8.675; D39 8.25,-8.675; D40 7.75,-8.675; D41 7.25,-8.675; D42 6.75,-8.675; D43 6.25,-8.675; D44 5.75,-8.675; D45 5.25,-8.675; D46 4.75,-8.675; D47 4.25,-8.675; D48 3.75,-8.675; D49 3.25,-8.675; D50 2.75,-8.675; D51 2.25,-8.675; D52 1.75,-8.675; D53 1.25,-8.675; D54 0.75,-8.675; D55 0.25,-8.675; D56 -0.25,-8.675; D57 -0.75,-8.675; D58 -1.25,-8.675; D59 -1.75,-8.675; D60 -2.25,-8.675; D61 -2.75,-8.675; D62 -3.25,-8.675; D63 -3.75,-8.675; D64 -4.25,-8.675; D65 -4.75,-8.675; D66 -5.25,-8.675; D67 -5.75,-8.675; D68 -6.25,-8.675; D69 -6.75,-8.675; D70 -7.25,-8.675; D71 -7.75,-8.675; D72 -8.25,-8.675; D73 -8.75,-8.675; D74 -9.25,-8.675; D75 -9.75,-8.675; D76 -10.25,-8.675; D77 -10.75,-8.675; D78 -11.25,-8.675; D79 -11.75,-8.675; D80 -12.25,-8.675; D81 -12.75,-8.675; D82 -13.25,-8.675; D83 -13.75,-8.675; D84 -14.25,-8.675; D85 -14.75,-8.675; D86 -15.25,-8.675; D87 -15.75,-8.675; D88 -16.25,-8.675; D89 -16.75,-8.675; D90 -17.25,-8.675; D91 -17.75,-8.675; D92 -18.25,-8.675; D93 -18.75,-8.675; D94 -19.25,-8.675; D95 -19.75,-8.675; D96 -20.25,-8.675; D97 -20.75,-8.675; D98 -21.25,-8.675; D99 -21.75,-8.675; D100 -22.25,-8.675; D101 -22.75,-8.675; D102 -23.25,-8.675; D103 -23.75,-8.675; D104 -24.25,-8.675; D105 -24.75,-8.675; D106 -25.25,-8.675; D107 -25.75,-8.675; D108 -26.25,-8.675; D109 -26.75,-8.675
smd 0.45 x 1.75: C1 27.325,-3.325; C110 -27.325,-3.325; D1 27.325,-8.675; D110 -27.325,-8.675
hole 0.9 at -28.85,-6
hole 1.6 at 28.85,-6
hole 0.9 at -28.85,6
hole 1.6 at 28.85,6
hole 0.9 at -28.85,-6
hole 1.6 at 28.85,-6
